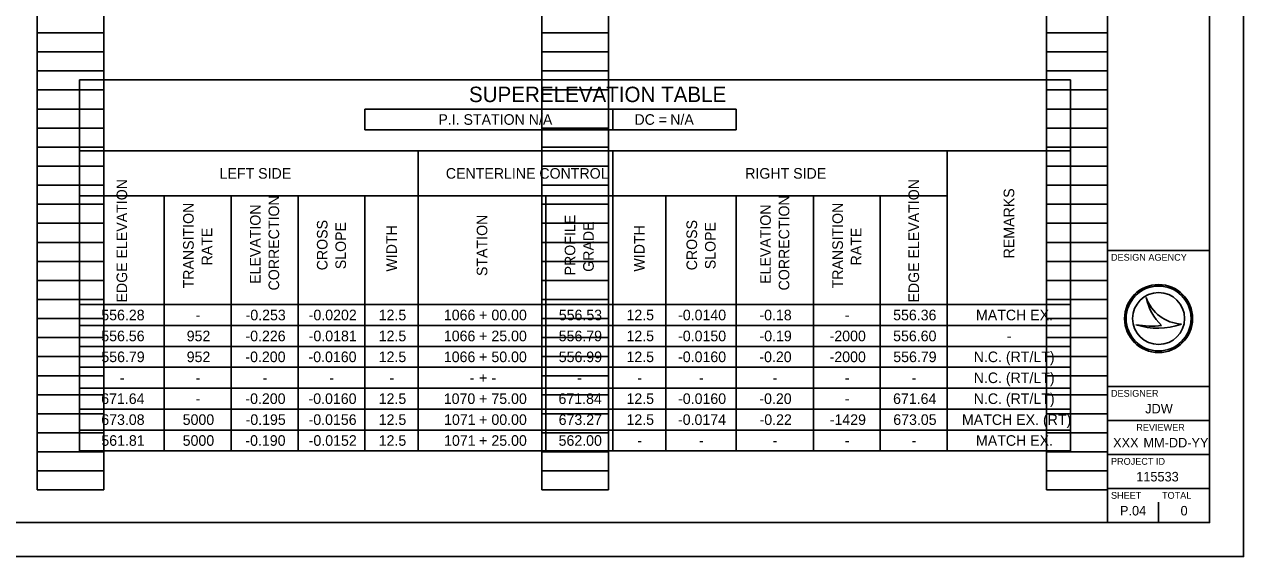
# Model space of a CAD drawing. Extents: x -15.5 to 34, y 0 to 22.
# Drawn here: x 16.07 to 34, y 0 to 7.82 of the extents above; entities that cross this region are included whole.
import ezdxf

# ---------------------------------------------------------------- set-up
doc = ezdxf.new("R2010")
doc.units = 0
for name, color, linetype in [('SH_Border', 7, 'Continuous'), ('SH_Cut_Line', 7, 'Continuous'), ('SH_Data', 7, 'Continuous'), ('SH_Text', 7, 'Continuous')]:
    doc.layers.add(name, color=color, linetype=linetype)

msp = doc.modelspace()

# ---------------------------------------------------------------- linework, layer by layer
at = {"layer": 'SH_Border'}
for p, q in [((32, 0.5), (32, 21.5)), ((32, 4.5), (33.5, 4.5)), ((32, 2.5), (33.5, 2.5)), ((32, 2), (33.5, 2)), ((32, 1.5), (33.5, 1.5)), ((32, 1), (33.5, 1))]:
    msp.add_line(p, q, dxfattribs=at)
msp.add_lwpolyline([(1.5, 21.5), (33.5, 21.5), (33.5, 0.5), (1.5, 0.5)], close=True, dxfattribs=at)
at = {"layer": 'SH_Cut_Line'}
msp.add_lwpolyline([(0, 0), (34, 0), (34, 22), (0, 22)], close=True, dxfattribs=at)
at = {"layer": 'SH_Data'}
for p, q in [((16.26, 0.98), (16.26, 21.14)), ((17.24, 0.98), (17.24, 21.14)), ((23.68, 0.98), (23.68, 21.14)), ((24.66, 0.98), (24.66, 21.14)), ((31.1, 0.98), (31.1, 21.14)), ((32, 0.98), (32, 21.14)), ((16.26, 7.7), (17.24, 7.7)), ((23.68, 7.7), (24.66, 7.7)), ((31.1, 7.7), (32, 7.7)), ((16.26, 7.42), (17.24, 7.42)), ((23.68, 7.42), (24.66, 7.42)), ((31.1, 7.42), (32, 7.42)), ((16.26, 7.14), (17.24, 7.14)), ((23.68, 7.14), (24.66, 7.14)), ((31.1, 7.14), (32, 7.14)), ((16.26, 6.86), (17.24, 6.86)), ((23.68, 6.86), (24.66, 6.86)), ((31.1, 6.86), (32, 6.86)), ((16.26, 6.58), (17.24, 6.58)), ((23.68, 6.58), (24.66, 6.58)), ((31.1, 6.58), (32, 6.58)), ((16.26, 6.3), (17.24, 6.3)), ((23.68, 6.3), (24.66, 6.3)), ((31.1, 6.3), (32, 6.3)), ((16.26, 6.02), (17.24, 6.02)), ((23.68, 6.02), (24.66, 6.02)), ((31.1, 6.02), (32, 6.02)), ((16.26, 5.74), (17.24, 5.74)), ((23.68, 5.74), (24.66, 5.74)), ((31.1, 5.74), (32, 5.74)), ((16.26, 5.46), (17.24, 5.46)), ((23.68, 5.46), (24.66, 5.46)), ((31.1, 5.46), (32, 5.46)), ((16.26, 5.18), (17.24, 5.18)), ((23.68, 5.18), (24.66, 5.18)), ((31.1, 5.18), (32, 5.18)), ((16.26, 4.9), (17.24, 4.9)), ((23.68, 4.9), (24.66, 4.9)), ((31.1, 4.9), (32, 4.9)), ((16.26, 4.62), (17.24, 4.62)), ((23.68, 4.62), (24.66, 4.62)), ((31.1, 4.62), (32, 4.62)), ((16.26, 4.34), (17.24, 4.34)), ((23.68, 4.34), (24.66, 4.34)), ((31.1, 4.34), (32, 4.34)), ((16.26, 4.06), (17.24, 4.06)), ((23.68, 4.06), (24.66, 4.06)), ((31.1, 4.06), (32, 4.06)), ((16.26, 3.78), (17.24, 3.78)), ((23.68, 3.78), (24.66, 3.78)), ((31.1, 3.78), (32, 3.78)), ((32.567, 3.81), (32.567, 3.81)), ((16.26, 3.5), (17.24, 3.5)), ((23.68, 3.5), (24.66, 3.5)), ((31.1, 3.5), (32, 3.5)), ((32.417, 3.41), (32.417, 3.41)), ((32.75, 3.5), (32.75, 3.5)), ((33.087, 3.419), (33.087, 3.419)), ((16.26, 3.22), (17.24, 3.22)), ((23.68, 3.22), (24.66, 3.22)), ((31.1, 3.22), (32, 3.22)), ((16.26, 2.94), (17.24, 2.94)), ((23.68, 2.94), (24.66, 2.94)), ((31.1, 2.94), (32, 2.94)), ((16.26, 2.66), (17.24, 2.66)), ((23.68, 2.66), (24.66, 2.66)), ((31.1, 2.66), (32, 2.66)), ((16.26, 2.38), (17.24, 2.38)), ((23.68, 2.38), (24.66, 2.38)), ((31.1, 2.38), (32, 2.38)), ((16.26, 2.1), (17.24, 2.1)), ((23.68, 2.1), (24.66, 2.1)), ((31.1, 2.1), (32, 2.1)), ((16.26, 1.82), (17.24, 1.82)), ((23.68, 1.82), (24.66, 1.82)), ((31.1, 1.82), (32, 1.82)), ((16.26, 1.54), (17.24, 1.54)), ((23.68, 1.54), (24.66, 1.54)), ((31.1, 1.54), (32, 1.54)), ((16.26, 1.26), (17.24, 1.26)), ((23.68, 1.26), (24.66, 1.26)), ((31.1, 1.26), (32, 1.26)), ((16.26, 0.98), (17.24, 0.98)), ((23.68, 0.98), (24.66, 0.98)), ((31.1, 0.98), (32, 0.98)), ((32.75, 0.5), (32.75, 0.8)), ((32.375, 0.675), (32.375, 0.675))]:
    msp.add_line(p, q, dxfattribs=at)
for radius in [0.5, 0.477, 0.477, 0.382]:
    msp.add_circle((32.75, 3.5), radius, dxfattribs=at)
for centre, radius, start, end in [((33.116, 3.998), 0.58, 198.9257, 198.9319), ((33.347, 3.97), 0.796, 191.6379, 191.6421), ((33.116, 3.998), 0.58, 198.9319, 267.1657), ((33.347, 3.97), 0.796, 191.6421, 226.0947), ((32.739, 4.37), 1.013, 251.4576, 290.0832), ((32.648, 4.654), 1.266, 259.4964, 259.4995), ((32.739, 4.37), 1.013, 251.4527, 251.4576), ((32.648, 4.654), 1.266, 259.4995, 276.6672)]:
    msp.add_arc(centre, radius, start, end, dxfattribs=at)
at = {"layer": 'SH_Text'}
for p, q in [((16.884, 7.01), (31.456, 7.01)), ((16.884, 7.01), (16.884, 1.553)), ((31.456, 7.01), (31.456, 1.553)), ((21.08, 6.579), (26.537, 6.579)), ((21.08, 6.579), (21.08, 6.272)), ((24.723, 6.579), (24.723, 6.272)), ((26.537, 6.579), (26.537, 6.272)), ((21.08, 6.272), (26.537, 6.272)), ((16.884, 5.965), (31.456, 5.965)), ((21.864, 5.965), (21.864, 1.553)), ((24.723, 5.965), (24.723, 1.553)), ((29.642, 5.965), (29.642, 1.553)), ((16.884, 5.304), (29.642, 5.304)), ((18.129, 5.304), (18.129, 1.553)), ((19.113, 5.304), (19.113, 1.553)), ((20.097, 5.304), (20.097, 1.553)), ((21.08, 5.304), (21.08, 1.553)), ((23.74, 5.304), (23.74, 1.553)), ((25.507, 5.304), (25.507, 1.553)), ((26.537, 5.304), (26.537, 1.553)), ((27.675, 5.304), (27.675, 1.553)), ((28.658, 5.304), (28.658, 1.553)), ((16.884, 3.705), (31.456, 3.705)), ((16.884, 3.398), (31.456, 3.398)), ((16.884, 3.09), (31.456, 3.09)), ((16.884, 2.783), (31.456, 2.783)), ((16.884, 2.475), (31.456, 2.475)), ((16.884, 2.168), (31.456, 2.168)), ((16.884, 1.861), (31.456, 1.861)), ((16.884, 1.553), (31.456, 1.553))]:
    msp.add_line(p, q, dxfattribs=at)

# ---------------------------------------------------------------- texts
at = {"layer": 'SH_Data'}
for s, height, p in [('DESIGN AGENCY', 0.1, (32.05, 4.35)), ('DESIGNER', 0.1, (32.05, 2.35)), ('JDW', 0.14, (32.553, 2.105)), ('REVIEWER', 0.1, (32.422, 1.85)), ('XXX', 0.14, (32.081, 1.605)), ('MM-DD-YY', 0.14, (32.527, 1.605)), ('PROJECT ID', 0.1, (32.05, 1.35)), ('115533', 0.14, (32.421, 1.105)), ('SHEET', 0.1, (32.05, 0.85)), ('TOTAL', 0.1, (32.8, 0.85)), ('P.04', 0.14, (32.182, 0.605)), ('0', 0.14, (33.073, 0.605))]:
    msp.add_text(s, height=height, dxfattribs=at).set_placement(p)
at = {"layer": 'SH_Text'}
for s, height, p in [('SUPERELEVATION TABLE', 0.22626, (22.61, 6.682)), ('P.I. STATION N/A', 0.15556, (22.16, 6.348)), ('DC =', 0.1556, (25.043, 6.348)), ('N/A', 0.1556, (25.569, 6.348)), ('LEFT SIDE', 0.1556, (18.944, 5.556)), ('CENTERLINE CONTROL', 0.15556, (22.27, 5.556)), ('RIGHT SIDE', 0.1556, (26.672, 5.556)), ('556.28', 0.1556, (17.204, 3.474)), ('-0.253', 0.1556, (19.326, 3.474)), ('-0.0202', 0.1556, (20.254, 3.474)), ('12.5', 0.1556, (21.283, 3.474)), ('1066', 0.1556, (22.241, 3.474)), ('+', 0.156, (22.759, 3.474)), ('00.00', 0.1556, (22.94, 3.474)), ('556.53', 0.1556, (23.931, 3.474)), ('12.5', 0.1556, (24.926, 3.474)), ('-0.0140', 0.1556, (25.685, 3.474)), ('-0.18', 0.1556, (26.881, 3.474)), ('556.36', 0.1556, (28.847, 3.474)), ('MATCH EX.', 0.1556, (30.065, 3.474)), ('-', 0.156, (18.591, 3.474)), ('-', 0.156, (28.136, 3.474)), ('556.56', 0.1556, (17.204, 3.166)), ('952', 0.1556, (18.46, 3.166)), ('-0.226', 0.1556, (19.324, 3.166)), ('-0.0181', 0.1556, (20.254, 3.166)), ('12.5', 0.1556, (21.283, 3.166)), ('1066', 0.1556, (22.241, 3.166)), ('+', 0.156, (22.759, 3.166)), ('25.00', 0.1556, (22.94, 3.166)), ('556.79', 0.1556, (23.93, 3.166)), ('12.5', 0.1556, (24.926, 3.166)), ('-0.0150', 0.1556, (25.685, 3.166)), ('-0.19', 0.1556, (26.882, 3.166)), ('-2000', 0.1556, (27.913, 3.166)), ('556.60', 0.1556, (28.847, 3.166)), ('-', 0.156, (30.519, 3.166)), ('556.79', 0.1556, (17.205, 2.859)), ('952', 0.1556, (18.46, 2.859)), ('-0.200', 0.1556, (19.323, 2.859)), ('-0.0160', 0.1556, (20.251, 2.859)), ('12.5', 0.1556, (21.283, 2.859)), ('1066', 0.1556, (22.241, 2.859)), ('+', 0.156, (22.759, 2.859)), ('50.00', 0.1556, (22.94, 2.859)), ('556.99', 0.1556, (23.93, 2.859)), ('12.5', 0.1556, (24.926, 2.859)), ('-0.0160', 0.1556, (25.685, 2.859)), ('-0.20', 0.1556, (26.88, 2.859)), ('-2000', 0.1556, (27.913, 2.859)), ('556.79', 0.1556, (28.849, 2.859)), ('N.C. (RT/LT)', 0.15556, (30.031, 2.859)), ('N.C. (RT/LT)', 0.15556, (30.031, 2.551)), ('-', 0.156, (17.477, 2.551)), ('-', 0.156, (18.591, 2.551)), ('-', 0.156, (19.575, 2.551)), ('-', 0.156, (20.558, 2.551)), ('-', 0.156, (21.442, 2.551)), ('-', 0.156, (22.619, 2.551)), ('+', 0.156, (22.759, 2.551)), ('-', 0.156, (22.94, 2.551)), ('-', 0.156, (24.201, 2.551)), ('-', 0.156, (25.085, 2.551)), ('-', 0.156, (25.992, 2.551)), ('-', 0.156, (27.076, 2.551)), ('-', 0.156, (28.136, 2.551)), ('-', 0.156, (29.12, 2.551)), ('671.64', 0.1556, (17.203, 2.244)), ('-0.200', 0.1556, (19.323, 2.244)), ('-0.0160', 0.1556, (20.251, 2.244)), ('12.5', 0.1556, (21.283, 2.244)), ('1070', 0.1556, (22.24, 2.244)), ('+', 0.156, (22.759, 2.244)), ('75.00', 0.1556, (22.94, 2.244)), ('671.84', 0.1556, (23.927, 2.244)), ('12.5', 0.1556, (24.926, 2.244)), ('-0.0160', 0.1556, (25.685, 2.244)), ('-0.20', 0.1556, (26.88, 2.244)), ('671.64', 0.1556, (28.846, 2.244)), ('N.C. (RT/LT)', 0.15556, (30.031, 2.244)), ('-', 0.156, (18.591, 2.244)), ('-', 0.156, (28.136, 2.244)), ('673.08', 0.1556, (17.204, 1.936)), ('5000', 0.1556, (18.401, 1.936)), ('-0.195', 0.1556, (19.326, 1.936)), ('-0.0156', 0.1556, (20.252, 1.936)), ('12.5', 0.1556, (21.283, 1.936)), ('1071', 0.1556, (22.244, 1.936)), ('+', 0.156, (22.759, 1.936)), ('00.00', 0.1556, (22.94, 1.936)), ('673.27', 0.1556, (23.929, 1.936)), ('12.5', 0.1556, (24.926, 1.936)), ('-0.0174', 0.1556, (25.684, 1.936)), ('-0.22', 0.1556, (26.883, 1.936)), ('-1429', 0.1556, (27.915, 1.936)), ('673.05', 0.1556, (28.849, 1.936)), ('MATCH EX. (RT)', 0.15556, (29.859, 1.936)), ('561.81', 0.1556, (17.205, 1.629)), ('5000', 0.1556, (18.401, 1.629)), ('-0.190', 0.1556, (19.323, 1.629)), ('-0.0152', 0.1556, (20.254, 1.629)), ('12.5', 0.1556, (21.283, 1.629)), ('1071', 0.1556, (22.244, 1.629)), ('+', 0.156, (22.759, 1.629)), ('25.00', 0.1556, (22.94, 1.629)), ('562.00', 0.1556, (23.928, 1.629)), ('-', 0.156, (25.085, 1.629)), ('-', 0.156, (25.992, 1.629)), ('-', 0.156, (27.076, 1.629)), ('-', 0.156, (28.136, 1.629)), ('-', 0.156, (29.12, 1.629)), ('MATCH EX.', 0.1556, (30.065, 1.629))]:
    msp.add_text(s, height=height, dxfattribs=at).set_placement(p)
for s, height, p in [('EDGE ELEVATION', 0.15556, (17.584, 3.736)), ('EDGE ELEVATION', 0.15556, (29.228, 3.736)), ('REMARKS', 0.1556, (30.627, 4.385)), ('CORRECTION', 0.1556, (19.819, 3.913)), ('CORRECTION', 0.1556, (27.32, 3.913)), ('TRANSITION ', 0.15556, (18.563, 3.943)), ('ELEVATION ', 0.1556, (19.546, 4.009)), ('ELEVATION ', 0.1556, (27.048, 4.009)), ('TRANSITION       ', 0.15556, (28.108, 3.943)), ('CROSS                  ', 0.15556, (20.53, 4.209)), ('SLOPE', 0.1556, (20.802, 4.225)), ('WIDTH', 0.1556, (21.55, 4.19)), ('STATION', 0.1556, (22.88, 4.125)), ('PROFILE           ', 0.15556, (24.173, 4.134)), ('GRADE', 0.1556, (24.445, 4.187)), ('WIDTH', 0.1556, (25.193, 4.19)), ('CROSS                 ', 0.15556, (25.964, 4.209)), ('SLOPE', 0.1556, (26.236, 4.225)), ('RATE', 0.1556, (18.835, 4.281)), ('RATE', 0.1556, (28.38, 4.281))]:
    msp.add_text(s, height=height, rotation=90, dxfattribs=at).set_placement(p)

doc.saveas('drawing.dxf')
